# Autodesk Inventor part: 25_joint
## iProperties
Created: 2002-11
Part Number: 25_joint
Material: PVC - canalisation
Document SubType Name: Modélisation
Designer: FIEVET
Control State: 0
Master: False
Checked Out: False
Shininess: 69.0
Length Units: 11269
Angle Units: 11279
Time Units: 11290
Mass Units: 11283
Length Display Precision: 3
Angle Display Precision: 2
Compacted: True
Density: 1.4
Volumn: 0.11309733552923246
Area: 3.392920065876976
PropertySet Name: Model Information
Author: FIEVET
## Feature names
1. Extrusion1
